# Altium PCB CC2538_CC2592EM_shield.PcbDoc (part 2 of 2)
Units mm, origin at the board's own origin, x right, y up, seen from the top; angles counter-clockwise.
Board outline 41.63 x 56.78 mm, 4 copper layers (TOP, L2, L3, BOTTOM), stack 1.596 mm thick; 77 components, 70 nets, 284 pads, 581 vias.
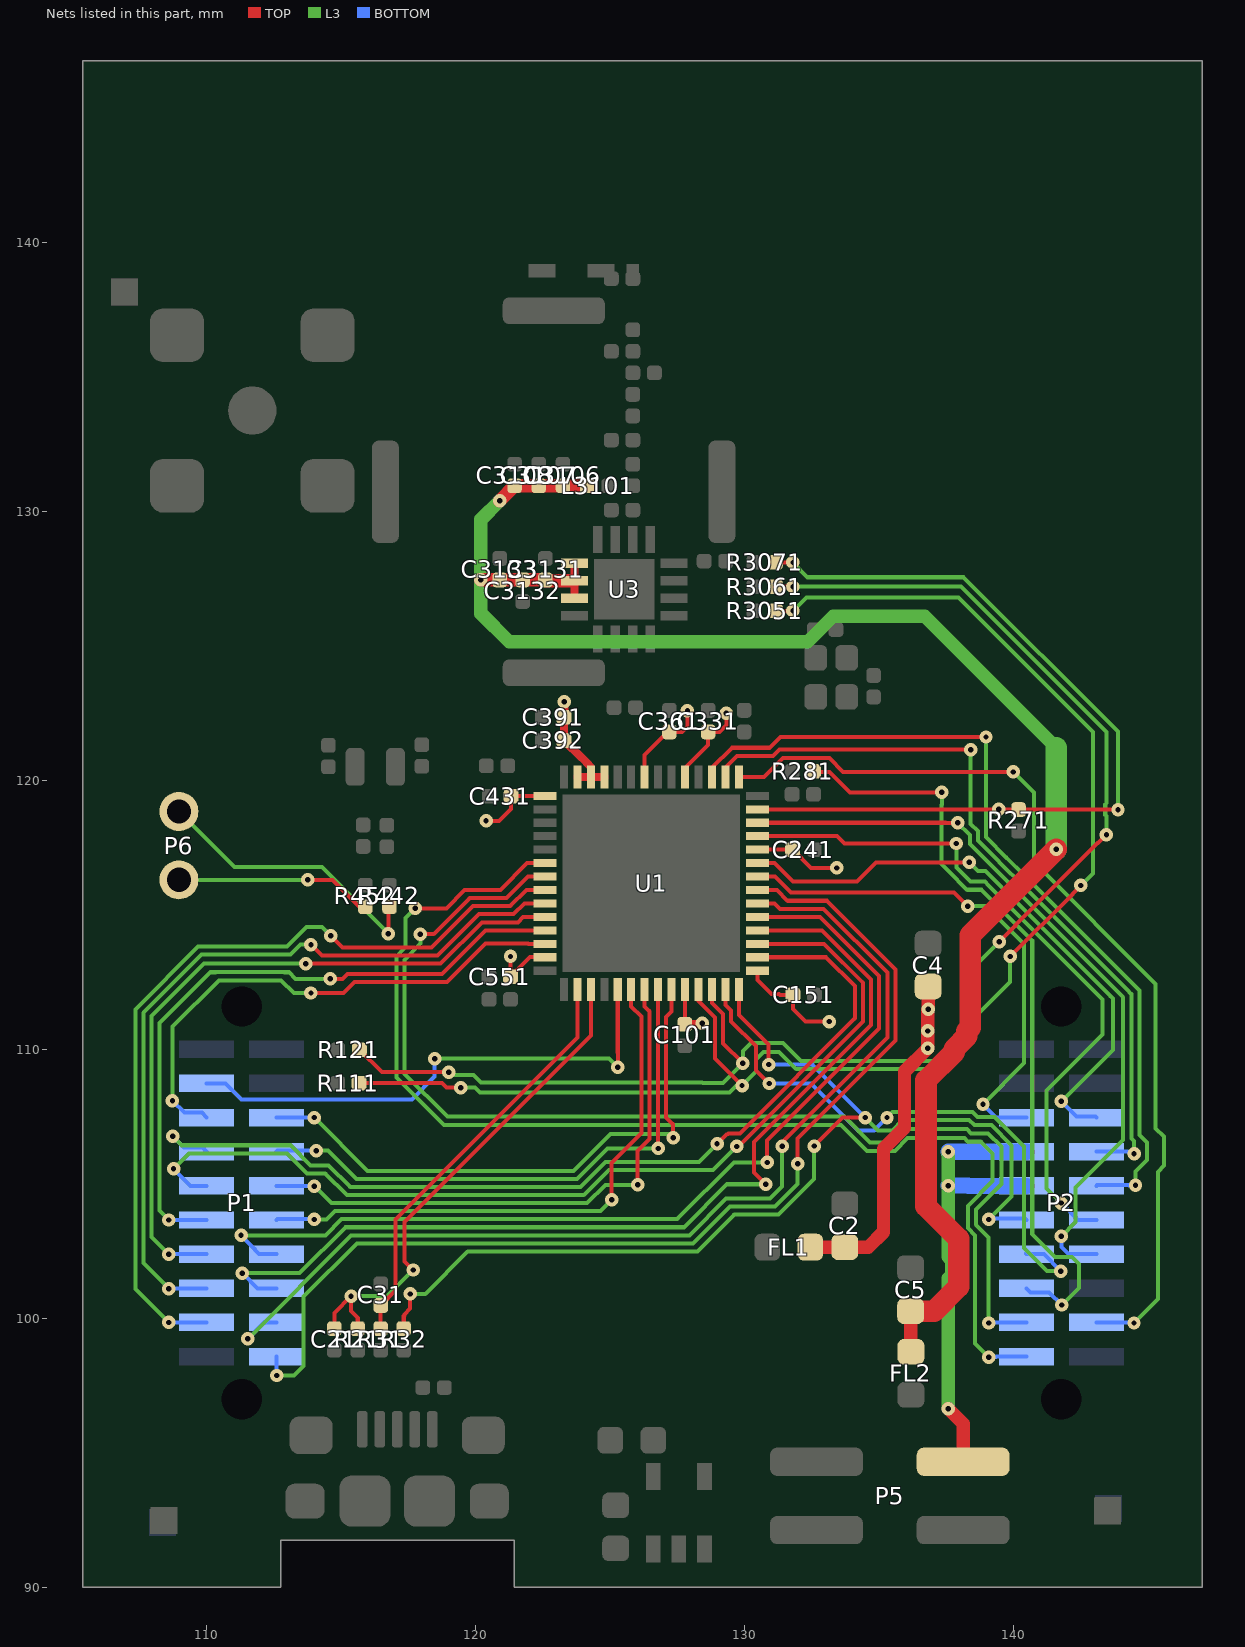
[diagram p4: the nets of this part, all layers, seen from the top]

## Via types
v1: diameter 0.5, hole 0.2, TOP to BOTTOM, 581 vias

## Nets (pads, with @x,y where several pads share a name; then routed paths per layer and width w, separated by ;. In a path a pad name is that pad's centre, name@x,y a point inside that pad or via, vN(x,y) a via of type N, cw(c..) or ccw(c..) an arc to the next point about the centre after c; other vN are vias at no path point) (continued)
NRESET: P2.15 R281.1 | length 28.8
  TOP w0.15: R281.1@132.57,120.33 132.59,120.31 133.17,120.31 133.93,119.55 v1(137.34,119.55)
  L3 w0.15: v1(137.34,119.55) 137.34,119.098 137.33,119.088 137.33,116.884 137.585,116.629 ; 137.585,116.628 138.283,115.93 138.808,115.93 ; 138.81,115.929 138.833,115.905 139.764,114.974 ; 139.765,114.974 140.7,114.039 140.7,103.13 141.55,102.28 142.17,102.28 142.44,102.01 142.44,101.13 v1(141.8,100.49) ; 138.808,115.93 138.809,115.929
  BOTTOM w0.15: P2.15@140.48,101.11 140.63,100.96 141.33,100.96 v1(141.8,100.49)
PA0: P1.7 U1.16 | length 35.5
  TOP w0.15: v1(128.98,106.48) 129.33,106.829 129.379,106.851 129.398,106.87 129.828,106.87 134.11,111.152 134.11,112.347 133.037,113.42 U1.16@130.49,113.42
  L3 w0.15: v1(108.74,106.76) 109.07,106.43 113.121,106.43 113.866,105.685 114.536,105.685 115.341,104.88 123.899,104.88 124.829,105.81 128.31,105.81 v1(128.98,106.48)
  BOTTOM w0.15: v1(108.74,106.76) 109.16,106.34 109.85,106.34 P1.7@110,106.19
PA1: P1.9 U1.17 | length 36.6
  TOP w0.15: v1(129.71,106.385) 129.716,106.39 129.773,106.39 134.41,111.027 134.41,112.472 132.962,113.92 U1.17@130.49,113.92
  L3 w0.15: v1(108.77,105.55) 109.35,106.13 112.996,106.13 113.741,105.385 114.411,105.385 115.216,104.58 124.024,104.58 124.954,105.51 128.836,105.51 v1(129.71,106.385)
  BOTTOM w0.15: v1(108.77,105.55) 109.4,104.92 P1.9@110,104.92
PA2: P1.16 U1.18 | length 36.9
  TOP w0.15: U1.18@130.49,114.42 132.887,114.42 134.71,112.597 134.71,110.902 130.36,106.552 130.36,105.41 v1(130.79,104.98)
  L3 w0.15: v1(111.33,101.674) 113.454,101.674 115.16,103.38 127.75,103.38 129.35,104.98 v1(130.79,104.98)
  BOTTOM w0.15: v1(111.33,101.674) 111.894,101.11 P1.16@112.604,101.11
PA3: P1.14 U1.19 | length 36.4
  TOP w0.15: U1.19@130.49,114.921 132.811,114.921 135.01,112.722 135.01,110.777 133.745,109.511 ; v1(130.84,105.79) 130.84,106.607 133.744,109.511
  L3 w0.15: v1(111.28,103.082) 114.422,103.082 115.02,103.68 127.5,103.68 129.61,105.79 v1(130.84,105.79)
  BOTTOM w0.15: v1(111.28,103.082) 111.8,102.562 111.8,102.53 111.95,102.38 P1.14@112.604,102.38
PA4: P1.18 U1.20 | length 39
  TOP w0.15: U1.20@130.49,115.421 131.118,115.421 131.318,115.221 132.936,115.221 135.311,112.846 135.311,110.441 131.4,106.53 v1(131.4,106.39)
  L3 w0.15: v1(111.53,99.23) 115.37,103.07 115.456,103.07 115.466,103.08 127.95,103.08 129.32,104.45 130.951,104.45 131.4,104.902 v1(131.4,106.39)
  BOTTOM w0.15: v1(111.53,99.23) 112.14,99.84 P1.18@112.604,99.84
PA5: P1.20 U1.21 | length 40.4
  TOP w0.15: U1.21@130.49,115.919 131.211,115.919 131.609,115.521 133.061,115.521 135.611,112.971 135.611,110.316 131.98,106.685 v1(131.98,105.74)
  L3 w0.15: v1(112.61,97.868) 113.252,97.868 113.61,98.226 113.61,100.8 115.59,102.78 128.09,102.78 129.46,104.15 131.143,104.15 131.98,104.987 v1(131.98,105.74)
  BOTTOM w0.15: P1.20@112.604,98.57 112.604,98.086 112.61,98.08 v1(112.61,97.868)
PA6: P2.5 U1.22 | length 19.4
  TOP w0.15: U1.22@130.49,116.419 131.141,116.419 131.73,115.83 137.79,115.83 v1(138.3,115.32)
  L3 w0.15: v1(138.3,115.32) 138.993,115.32 139.639,114.674 ; v1(138.87,107.95) 140.4,109.48 140.4,113.914 139.64,114.674
  BOTTOM w0.15: v1(138.87,107.95) 139.36,107.46 P2.5@140.48,107.46
PA7: P2.6 U1.23 | length 22.1
  TOP w0.15: U1.23@130.49,116.92 131.118,116.92 131.798,116.24 134.179,116.24 134.889,116.95 v1(138.36,116.95)
  L3 w0.15: v1(138.36,116.95) 138.68,116.63 138.958,116.63 139.059,116.529 139.061,116.529 139.283,116.306 140.014,115.574 ; 140.015,115.574 143.62,111.969 ; v1(141.78,108.06) 143.7,109.98 143.7,111.888 143.62,111.968
  BOTTOM w0.15: v1(141.78,108.06) 142.34,107.5 143.044,107.5 P2.6@143.084,107.46
PB0: P1.3 U1.5 | length 19.6
  TOP w0.15: U1.5@125.288,112.221 125.288,109.87 125.29,109.868 v1(125.29,109.33)
  L3 w0.15: v1(118.48,109.65) 124.97,109.65 v1(125.29,109.33)
  BOTTOM w0.15: P1.3@110,108.73 110.7,108.73 111.3,108.13 117.63,108.13 118.48,108.98 v1(118.48,109.65)
PB1: P1.5 U1.54 | length 19.8
  TOP w0.15: v1(113.88,112.09) 115.084,112.09 115.491,112.497 115.512,112.501 118.793,112.501 118.796,112.504 118.879,112.504 118.881,112.506 118.946,112.506 120.365,113.925 121.955,113.925 121.96,113.92 U1.54@122.588,113.92
  L3 w0.15: v1(108.73,108.08) 108.73,110.84 110.454,112.564 112.77,112.564 113.244,112.09 v1(113.88,112.09)
  BOTTOM w0.15: v1(108.73,108.08) 109.17,107.64 109.82,107.64 P1.5@110,107.46
PB2: P1.11 U1.53 | length 24.8
  TOP w0.15: v1(114.6,112.62) 115.052,112.62 115.233,112.801 118.668,112.801 118.671,112.804 118.754,112.804 120.369,114.419 121.664,114.419 121.665,114.42 U1.53@122.588,114.42
  L3 w0.15: v1(108.598,103.65) 108.25,103.998 108.25,110.97 110.143,112.863 110.328,112.863 110.329,112.864 112.895,112.864 ; v1(114.6,112.62) 113.31,112.62 113.067,112.863 112.896,112.863 ; 112.895,112.864 112.896,112.863
  BOTTOM w0.15: v1(108.598,103.65) P1.11@110,103.65
PB3: P1.13 U1.52 | length 26.7
  TOP w0.15: v1(113.68,113.18) 118.705,113.18 120.244,114.719 121.539,114.719 121.54,114.72 121.57,114.72 121.771,114.921 U1.52@122.588,114.921
  L3 w0.15: v1(108.59,102.38) 107.95,103.02 107.95,111.233 109.897,113.18 v1(113.68,113.18)
  BOTTOM w0.15: v1(108.59,102.38) P1.13@110,102.38
PB4: P1.15 U1.51 | length 29
  TOP w0.15: v1(113.88,113.89) 114.29,113.48 118.58,113.48 120.12,115.02 121.415,115.02 121.816,115.421 U1.51@122.588,115.421
  L3 w0.15: v1(108.598,101.1) 107.649,102.049 107.649,111.357 109.812,113.52 113.114,113.52 113.484,113.89 v1(113.88,113.89)
  BOTTOM w0.15: v1(108.598,101.1) 108.763,101.1 108.773,101.11 P1.15@110,101.11
PB5: P1.17 U1.50 | length 31.3
  TOP w0.15: v1(114.61,114.22) 115.05,113.78 118.37,113.78 119.91,115.32 121.29,115.32 121.889,115.919 U1.50@122.588,115.919
  L3 w0.15: v1(108.598,99.84) 107.35,101.088 107.35,101.923 107.349,101.924 107.349,111.482 109.687,113.82 112.989,113.82 113.709,114.54 114.29,114.54 v1(114.61,114.22)
  BOTTOM w0.15: v1(108.598,99.84) P1.17@110,99.84
PB6/JTAG_TDI: P2.17 U1.49 | length 43.3
  TOP w0.15: v1(117.95,114.28) 118.442,114.28 118.472,114.31 118.475,114.31 119.785,115.62 121.159,115.62 121.958,116.419 U1.49@122.588,116.419
  L3 w0.15: v1(117.95,114.28) 117.96,114.27 117.96,113.925 117.36,113.325 117.36,109.082 118.952,107.49 133.711,107.49 134.671,106.53 135.475,106.53 135.945,107 135.99,107 136.02,107.03 138.268,107.03 138.423,106.875 139.055,106.875 139.55,106.38 139.55,104.993 138.603,104.046 138.603,103.473 139.078,102.998 v1(139.078,99.82)
  BOTTOM w0.15: v1(139.078,99.82) 139.27,99.82 139.29,99.84 P2.17@140.48,99.84
PB7/JTAG_TDO: P2.19 U1.48 | length 45.5
  TOP w0.15: v1(117.76,115.24) 118.912,115.24 119.592,115.92 120.92,115.92 121.92,116.92 U1.48@122.588,116.92
  L3 w0.15: v1(117.76,115.24) 117.402,114.882 117.402,113.793 117.06,113.45 117.06,108.957 118.827,107.19 133.586,107.19 134.556,106.22 135.59,106.22 136.07,106.7 138.173,106.7 138.298,106.575 138.785,106.575 139.23,106.13 139.23,105.098 138.303,104.171 138.303,103.348 138.571,103.08 138.571,99.057 v1(139.078,98.55)
  BOTTOM w0.15: v1(139.078,98.55) 139.35,98.55 139.37,98.57 P2.19@140.48,98.57
PC0: P2.11 R32.2 U1.14 | length 40.1
  TOP w0.15: R32.2@117.33,99.61 117.33,100.087 117.35,100.107 117.35,100.14 117.57,100.36 v1(117.57,100.9) ; U1.14@129.789,112.221 129.789,111.576 129.795,111.57 129.795,111.549 129.797,111.547 129.797,111.399 129.801,111.37 129.802,111.364 129.802,111.278 130.9,110.18 v1(130.9,109.43) ; v1(132.59,106.4) 133.65,107.46 v1(134.49,107.46)
  L3 w0.15: v1(117.57,100.9) 118.13,100.9 119.71,102.48 128.25,102.48 129.62,103.85 131.268,103.85 132.585,105.167 132.585,105.697 132.59,105.702 v1(132.59,106.4) ; v1(134.49,107.46) 134.965,106.985 135.497,106.985 135.882,107.37 138.353,107.37 138.548,107.175 139.18,107.175 139.93,106.425 139.93,104.522 v1(139.078,103.67)
  BOTTOM w0.15: v1(130.9,109.43) 132.52,109.43 v1(134.49,107.46) ; v1(139.078,103.67) 139.22,103.67 139.25,103.7 140.43,103.7 P2.11@140.48,103.65
PC1: P2.13 U1.13 | length 22.2
  TOP w0.15: U1.13@129.289,112.221 129.289,111.651 129.495,111.445 129.495,111.424 129.497,111.422 129.497,111.378 129.502,111.342 129.502,111.038 130.425,110.115 130.425,109.218 v1(130.918,108.725)
  L3 w0.15: v1(135.3,107.46) 135.51,107.67 138.478,107.67 138.673,107.475 139.305,107.475 140.4,106.38 140.4,102.603 141.253,101.75 v1(141.76,101.75)
  BOTTOM w0.15: v1(130.918,108.725) 132.475,108.725 133.96,107.241 134.216,106.985 134.825,106.985 v1(135.3,107.46) ; P2.13@140.46,102.4 P2.13@140.48,102.38 141.13,102.38 v1(141.76,101.75)
PC2: R121.1 R3061.1 U1.12 | length 55.7
  TOP w0.15: R121.1@115.68,109.98 115.685,109.98 116.515,109.15 v1(119.01,109.15) ; U1.12@128.788,112.221 128.788,111.727 129.202,111.313 129.202,110.218 v1(129.94,109.48) ; R3061.1@131.15,127.2 v1(131.802,127.2) ; v1(139.48,114) 140.068,114.588 140.068,114.6 143.128,117.66 143.14,117.66 v1(143.46,117.98)
  L3 w0.15: v1(119.01,109.15) 119.115,109.045 119.932,109.045 120.207,108.77 128.428,108.77 128.453,108.745 129.205,108.745 v1(129.94,109.48) 129.94,109.932 130.248,110.24 131.427,110.24 131.709,109.959 132.103,109.565 137.055,109.565 138.29,110.8 138.29,112.81 v1(139.48,114) ; v1(131.802,127.2) 138.05,127.2 143.46,121.79 143.46,119.152 143.415,119.107 143.415,118.713 143.46,118.668 v1(143.46,117.98)
PC3: R111.1 R3051.1 U1.11 | length 56.2
  TOP w0.15: R111.1@115.67,108.74 118.748,108.74 118.918,108.57 v1(119.45,108.57) ; U1.11@128.29,112.221 128.29,111.8 128.902,111.188 128.902,109.658 v1(129.91,108.65) ; R3051.1@131.15,126.3 v1(131.802,126.3) ; v1(139.88,113.45) 142.19,115.76 142.19,115.77 v1(142.51,116.09)
  L3 w0.15: v1(119.45,108.57) 119.982,108.57 120.162,108.39 129.44,108.39 129.7,108.65 v1(129.91,108.65) ; v1@129.858,108.57 129.91,108.622 v1(129.91,108.65) ; v1(131.802,126.3) 132.302,126.8 137.96,126.8 142.96,121.8 142.96,121.092 142.965,121.087 142.965,120.693 142.96,120.688 142.96,116.54 v1(142.51,116.09) ; v1(139.88,113.45) 139.88,112.508 138.59,111.218 138.59,110.67 137.185,109.265 131.925,109.265 131.285,109.905 130.703,109.905 130.425,109.627 130.425,109.165 v1(129.91,108.65)
PC4: P1.6 U1.9 | length 21.9
  TOP w0.15: U1.9@127.289,112.221 127.29,111.403 127.09,111.203 127.09,107.47 127.35,107.21 v1(127.35,106.715)
  L3 w0.15: v1(114.006,107.46) 115.986,105.48 123.648,105.48 124.578,106.41 ; 124.579,106.41 124.819,106.65 125.019,106.849 127.216,106.849 v1(127.35,106.715)
  BOTTOM w0.15: P1.6@112.604,107.46 v1(114.006,107.46)
PC5: P1.8 U1.8 | length 21
  TOP w0.15: U1.8@126.789,112.221 126.789,111.593 126.79,111.592 v1(126.79,106.31)
  L3 w0.15: v1(114.07,106.23) 114.522,106.23 115.572,105.18 123.773,105.18 124.703,106.11 ; 124.704,106.11 124.904,106.31 v1(126.79,106.31)
  BOTTOM w0.15: P1.8@112.604,106.19 112.644,106.23 v1(114.07,106.23)
PC6: P1.10 U1.7 | length 21.5
  TOP w0.15: v1(126.03,104.96) 126.03,106.222 126.47,106.662 126.47,111.412 126.289,111.593 U1.7@126.289,112.221
  L3 w0.15: v1(114.006,104.91) 114.636,104.28 124.15,104.28 124.83,104.96 v1(126.03,104.96)
  BOTTOM w0.15: P1.10@112.604,104.92 113.996,104.92 v1(114.006,104.91)
PC7: P1.12 U1.6 | length 21.2
  TOP w0.15: v1(125.058,104.398) 125.058,105.768 126.17,106.88 126.17,111.212 125.789,111.593 U1.6@125.788,112.221
  L3 w0.15: v1(114.005,103.67) 114.457,103.67 114.767,103.98 124.64,103.98 v1(125.058,104.398)
  BOTTOM w0.15: P1.12@112.604,103.65 112.634,103.68 113.79,103.68 113.8,103.67 v1(114.005,103.67)
PD0: P2.12 U1.25 | length 26.1
  TOP w0.15: U1.25@130.49,117.921 133.449,117.921 133.72,117.65 v1(137.88,117.65)
  L3 w0.15: v1(137.88,117.65) 137.88,117.198 137.885,117.193 137.885,116.753 138.163,116.475 ; 138.164,116.475 138.409,116.23 138.933,116.23 138.934,116.229 138.936,116.229 139.07,116.093 139.889,115.274 ; 139.89,115.274 143.32,111.844 143.32,110.55 141.23,108.46 141.23,104.83 v1(141.78,104.28)
  BOTTOM w0.15: v1(141.78,104.28) 142.41,103.65 P2.12@143.084,103.65
PD1: P2.14 U1.26 | length 28.1
  TOP w0.15: U1.26@130.49,118.421 137.477,118.421 137.478,118.42 v1(137.93,118.42)
  L3 w0.15: v1(137.93,118.42) 138.38,117.97 138.38,117.633 139.184,116.829 139.186,116.829 139.496,116.519 140.139,115.875 143.92,112.094 ; v1(141.78,103.04) 142.31,103.57 142.31,104.859 143.84,106.389 ; 143.84,106.39 144.08,106.63 144.08,111.933 143.92,112.093
  BOTTOM w0.15: v1(141.78,103.04) 141.78,102.64 142.04,102.38 P2.14@143.084,102.38
PD2: R271.2 R3071.1 U1.27 | length 31.6
  TOP w0.15: U1.27@130.49,118.919 139.007,118.919 139.008,118.92 v1(139.46,118.92) 140.18,118.92 R271.2@140.19,118.91 v1(143.89,118.91) ; R3071.1@131.15,128.1 v1(131.802,128.1)
  L3 w0.15: v1(131.802,128.1) 132.352,127.55 138.15,127.55 143.89,121.81 v1(143.89,118.91)
PD3: P2.18 U1.29 | length 35.4
  TOP w0.15: U1.29@129.789,120.12 130.73,120.12 131.435,120.825 133.155,120.825 133.67,120.31 v1(140,120.31)
  L3 w0.15: v1(140,120.31) 140.76,119.55 140.76,116.957 145.29,112.427 145.29,107.06 145.6,106.75 145.6,105.67 145.37,105.44 145.37,100.705 v1(144.485,99.82)
  BOTTOM w0.15: P2.18@143.084,99.84 144.42,99.84 144.44,99.82 v1(144.485,99.82)
PD4: P2.8 U1.30 | length 28.7
  TOP w0.15: U1.30@129.289,120.12 129.289,120.469 129.73,120.91 131.061,120.91 131.276,121.125 131.285,121.125 131.3,121.14 v1(138.41,121.14)
  L3 w0.15: v1(138.41,121.14) 138.41,118.38 138.68,118.11 138.68,117.758 139.309,117.129 139.311,117.129 139.62,116.82 ; 139.621,116.82 140.264,116.176 ; 140.265,116.176 141.9,114.542 141.9,114.539 144.22,112.219 144.38,112.058 ; 144.38,112.057 144.39,112.047 144.39,106.685 144.486,106.589 v1(144.486,106.11)
  BOTTOM w0.15: P2.8@143.084,106.19 144.25,106.19 144.33,106.11 v1(144.486,106.11)
PD5: P2.10 U1.31 | length 31.8
  TOP w0.15: U1.31@128.788,120.12 128.788,120.469 129.531,121.21 130.936,121.21 131.151,121.425 131.155,121.425 131.345,121.615 138.523,121.615 138.528,121.61 v1(138.98,121.61)
  L3 w0.15: v1(138.98,121.61) 138.98,117.886 139.746,117.12 140.389,116.476 142.2,114.667 144.69,112.177 144.69,106.81 144.961,106.539 144.961,105.881 144.54,105.461 v1(144.54,104.94)
  BOTTOM w0.15: P2.10@143.084,104.92 143.114,104.95 144.29,104.95 144.3,104.94 v1(144.54,104.94)
PD6: P6.1 R442.1 | length 10.7
  TOP w0.15: v1(116.76,114.3) 116.76,115.26 R442.1@116.8,115.3
  L3 w0.15: P6.1@108.97,118.84 111.035,116.775 114.285,116.775 v1(116.76,114.3)
PD7: P6.2 R452.1 | length 7.5
  TOP w0.15: v1(113.76,116.3) 114.676,116.3 115.81,115.166 115.81,115.26 115.85,115.3 R452.1@115.9,115.3
  L3 w0.15: P6.2@108.97,116.3 v1(113.76,116.3)
USB_N: C21.1 R21.1 U1.3 | length 18.9
  TOP w0.15: C21.1@114.75,99.61 114.75,100.2 v1(115.37,100.82) 115.37,100.26 115.62,100.01 R21.1@115.62,99.61 ; v1(117.68,101.79) 117.36,102.11 117.36,103.576 124.29,110.506 U1.3@124.29,112.221
  L3 w0.15: v1(115.37,100.82) 116.71,100.82 v1(117.68,101.79)
USB_P: C31.1 R31.1 U1.2 | length 15.6
  TOP w0.15: R31.1@116.47,99.61 116.47,100.46 C31.1@116.48,100.47 116.48,100.475 117.025,101.02 117.025,103.666 123.79,110.431 123.79,111.592 123.789,111.593 U1.2@123.789,112.221
VDD_CC2538: C2.1 C4.1 C101.1 C151.1 C241.1 C331.1 C361.1 C391.1 C392.1 C431.1 C551.1 FL1.1 U1.10 U1.15 U1.24 U1.33 U1.36 U1.39 U1.40 U1.41 U1.43 U1.55 | length 38.1
  TOP w0.15: v1(120.39,118.49) 120.872,118.49 121.32,118.938 C431.1@121.32,119.41 121.797,119.41 121.806,119.419 U1.43@122.588,119.419 ; v1(121.3,113.45) 121.3,112.71 121.29,112.7 C551.1@121.3,112.7 122.03,113.43 122.578,113.43 U1.55@122.588,113.42 ; C391.1@123.29,122.33 C391.1@123.29,122.34 ; U1.36@126.289,120.12 126.289,120.934 127.145,121.79 127.2,121.79 C361.1@127.21,121.8 127.682,121.8 127.88,121.998 v1(127.88,122.58) ; C101.1@127.78,110.93 127.78,111.407 127.79,111.417 U1.10@127.79,112.221 ; U1.33@127.79,120.12 127.79,120.453 128.65,121.313 C331.1@128.65,121.8 129.072,121.8 129.327,122.055 129.327,122.493 v1(129.32,122.5) ; v1@128.395,110.93 v1(128.427,110.962) ; U1.15@130.49,112.919 130.49,112.567 131.012,112.046 131.288,112.046 131.314,112.02 C151.1@131.8,112.02 131.8,111.498 132.268,111.03 v1(133.15,111.03) ; U1.24@130.49,117.42 131.795,117.42 132.475,116.74 v1(133.43,116.74)
  TOP w0.3: v1(123.3,122.92) 123.3,122.34 123.29,122.33 C392.1@123.29,121.48 123.295,121.48 123.952,120.823 123.966,120.823 124.216,120.573 124.216,120.559 124.29,120.485 U1.40@124.29,120.12 ; U1.41@123.789,120.12 U1.40@124.29,120.12 ; U1.39@124.79,120.12 U1.40@124.29,120.12 ; C101.1@127.78,110.93 v1@128.395,110.93
  TOP w0.5: FL1.1@132.45,102.64 134.608,102.64 135.17,103.202 135.17,106.3 135.95,107.08 135.95,109.17 v1(136.82,110.04) v1(136.82,110.68) 136.82,111.47 v1(136.84,111.49) 136.84,112.32 C4.1@136.83,112.33
  L3 w0.15: v1@128.42,110.955 v1(128.427,110.962)
VDD_CC2592: C5.1 C3106.1 C3107.1 C3108.1 C3131.1 C3132.1 C3133.1 FL2.1 L3101.1 U3.13 U3.14 U3.15 | length 63.2
  TOP w0.15: C5.1@136.18,100.26 C5.1@136.19,100.26
  TOP w0.3: U3.15@123.675,126.775 U3.14@123.675,127.425 U3.13@123.675,128.075
  TOP w0.5: v1(120.2,127.45) C3133.1@120.9,127.45 C3132.1@121.75,127.45 C3131.1@122.6,127.45 122.625,127.425 U3.14@123.675,127.425 ; v1(120.9,130.4) C3108.1@121.45,130.95 C3107.1@122.35,130.95 C3106.1@123.25,130.95 L3101.1@124.15,130.95 ; FL2.1@136.19,98.74 FL2.1@136.19,98.75 C5.1@136.19,100.26
  TOP w0.8: C5.1@136.19,100.26 137.05,100.26 137.96,101.17 137.96,102.95 136.75,104.16 136.75,108.838 137.8,109.888 137.8,110.008 138.27,110.478 138.27,110.67 138.39,110.79 138.39,114.232 141.037,116.879 141.039,116.879 v1(141.59,117.43)
  L3 w0.5: v1(120.9,130.4) 120.2,129.7 v1(120.2,127.45) 120.2,126.2 121.25,125.15 132.35,125.15 133.3,126.1 136.7,126.1 141.59,121.21
  L3 w0.8: v1(141.59,117.43) 141.59,121.21
VDD_EB: P2.7 P2.9 P5.2 | length 17.7
  TOP w0.5: v1(137.58,96.63) 138.13,96.08 P5.2@138.13,94.66
  L3 w0.5: v1(137.58,96.63) 137.58,101.483 137.707,101.61 137.707,102.15 137.58,102.277 v1(137.58,104.93) v1(137.58,106.19)
  BOTTOM w0.6: v1(137.58,104.93) 138.312,104.93 138.322,104.92 P2.9@140.48,104.92 ; v1(137.58,106.19) P2.7@140.48,106.19
pads on no net: "P1. " "P2. " Designator1.1 Designator1.2 Designator1.3 FIDU1.1 FIDU2.1 FIDU3.1 FIDU4.1 FIDU5.1 FIDU6.1 P2.3 P5.4 U2.4

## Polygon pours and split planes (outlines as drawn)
VDD_CC2538 on L3 (solid, pour order 38): 724 vertices, not listed, extent 120,109.7 138.3,124.748
GND on L3 (solid, pour order 36): 132 vertices, not listed, extent 125.372,103.907 128.645,105.283
GND on L3 (solid, pour order 34): 66 vertices, not listed, extent 125.653,108.972 129.473,109.471
GND on L3 (solid, pour order 32): 77 vertices, not listed, extent 138.529,111.619 139.653,113.423
GND on L3 (solid, pour order 30): 107 vertices, not listed, extent 140.927,108.619 143.093,111.85
GND on L3 (solid, pour order 28): 140 vertices, not listed, extent 138.577,108.947 140.173,112.339
GND on L3 (solid, pour order 26): 67 vertices, not listed, extent 140.927,112.293 142.044,113.779
GND on L3 (solid, pour order 24): 149 vertices, not listed, extent 136.936,116.165 142.738,126.573
GND on L3 (solid, pour order 22): 378 vertices, not listed, extent 132.638,117.216 141.038,125.698
GND on L3 (solid, pour order 20): 162 vertices, not listed, extent 105.901,90.501 146.499,139.2
N362623 on L3 (solid, pour order 0): 91 vertices, not listed, extent 123.45,113 129.7,120.609
GND on TOP (solid, pour order 14): 208 vertices, not listed, extent 130.938,111.135 133.883,113.193
GND on TOP (solid, pour order 12): 348 vertices, not listed, extent 133.44,107.687 138.122,115.603
GND on TOP (solid, pour order 10): 181 vertices, not listed, extent 132.215,116.467 137.642,117.694
GND on TOP (solid, pour order 8): 127 vertices, not listed, extent 132.066,119.146 133.872,120.083
GND on TOP (solid, pour order 6): 739 vertices, not listed, extent 105.901,90.501 146.499,139.2
GND on TOP (solid, pour order 4): 121.45,138.2 121.45,139.2 125.2,139.2 125.2,138.2 121.45,138.2
N355972 on TOP (solid, pour order 2): 31 vertices, not listed, extent 111.668,132.983 113.305,134.517
GND on L2 (solid, pour order 16): 168 vertices, not listed, extent 105.901,90.501 146.499,139.2
GND on BOTTOM (solid, pour order 18): 217 vertices, not listed, extent 105.901,90.501 146.499,139.2
no net on Top Overlay (solid): 115 vertices, not listed, extent 131.837,140.412 133.153,141.91
no net on Top Overlay (solid): 113 vertices, not listed, extent 135.036,138.652 136.075,139.835
no net on Top Overlay (solid): 113 vertices, not listed, extent 142.424,138.652 143.464,139.835
no net on Top Overlay (solid): 112 vertices, not listed, extent 133.986,140.412 135.144,141.603
no net on Top Overlay (solid): 99 vertices, not listed, extent 135.122,140.412 136.31,141.603
no net on Top Overlay (solid): 313 vertices, not listed, extent 136.127,138.649 137.351,139.833
no net on Top Overlay (solid): 164 vertices, not listed, extent 137.248,138.652 138.485,139.839
no net on Top Overlay (solid): 169 vertices, not listed, extent 138.545,138.65 140.047,139.839
no net on Top Overlay (solid): 128 vertices, not listed, extent 140.129,138.65 141.161,139.839
no net on Top Overlay (solid): 128 vertices, not listed, extent 132.934,140.412 133.965,141.601
no net on Top Overlay (solid): 92 vertices, not listed, extent 132.238,138.65 132.76,140.196
no net on Top Overlay (solid): 139 vertices, not listed, extent 132.823,138.652 134.048,139.839
no net on Top Overlay (solid): 139 vertices, not listed, extent 141.172,138.652 142.397,139.839
no net on Top Overlay (solid): 188 vertices, not listed, extent 143.516,138.62 144.485,139.858
no net on Top Overlay (solid): 188 vertices, not listed, extent 134.072,138.614 135.042,139.851
no net on Top Overlay (solid): 188 vertices, not listed, extent 136.292,140.376 137.262,141.614
no net on Top Overlay (solid): 199 vertices, not listed, extent 127.598,139.02 131.321,142.65
no net on Top Overlay (solid): 129.856,142.031 129.947,142.429 130.363,142.429 130.272,142.031 129.856,142.031
no net on Top Overlay (solid): 129.856,141.975 129.539,140.407 129.955,140.407 130.272,141.975 129.856,141.975
no net on Top Overlay (solid): 115 vertices, not listed, extent 131.837,140.412 133.153,141.91
no net on Top Overlay (solid): 113 vertices, not listed, extent 135.036,138.652 136.075,139.835
no net on Top Overlay (solid): 113 vertices, not listed, extent 142.424,138.652 143.464,139.835
no net on Top Overlay (solid): 112 vertices, not listed, extent 133.986,140.412 135.144,141.603
no net on Top Overlay (solid): 99 vertices, not listed, extent 135.122,140.412 136.31,141.603
no net on Top Overlay (solid): 313 vertices, not listed, extent 136.127,138.649 137.351,139.833
no net on Top Overlay (solid): 164 vertices, not listed, extent 137.248,138.652 138.485,139.839
no net on Top Overlay (solid): 169 vertices, not listed, extent 138.545,138.65 140.047,139.839
no net on Top Overlay (solid): 128 vertices, not listed, extent 140.129,138.65 141.161,139.839
no net on Top Overlay (solid): 128 vertices, not listed, extent 132.934,140.412 133.965,141.601
no net on Top Overlay (solid): 92 vertices, not listed, extent 132.238,138.65 132.76,140.196
no net on Top Overlay (solid): 139 vertices, not listed, extent 132.823,138.652 134.048,139.839
no net on Top Overlay (solid): 139 vertices, not listed, extent 141.172,138.652 142.397,139.839
no net on Top Overlay (solid): 188 vertices, not listed, extent 143.516,138.62 144.485,139.858
no net on Top Overlay (solid): 188 vertices, not listed, extent 134.072,138.614 135.042,139.851
no net on Top Overlay (solid): 188 vertices, not listed, extent 136.292,140.376 137.262,141.614
no net on Top Overlay (solid): 199 vertices, not listed, extent 127.598,139.02 131.321,142.65
no net on Top Overlay (solid): 129.856,142.031 129.947,142.429 130.363,142.429 130.272,142.031 129.856,142.031
no net on Top Overlay (solid): 129.856,141.975 129.539,140.407 129.955,140.407 130.272,141.975 129.856,141.975
no net on Top Overlay (solid): 82 vertices, not listed, extent 110.568,139.099 113.186,144.095
no net on Top Overlay (solid): 82 vertices, not listed, extent 106.282,139.099 108.9,144.095
no net on Top Overlay (solid): 82 vertices, not listed, extent 110.568,139.099 113.186,144.095
no net on Top Overlay (solid): 82 vertices, not listed, extent 106.282,139.099 108.9,144.095

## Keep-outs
Keep-Out Layer:
  lines w0.025: 105.4,90 105.4,146.75 147,146.75 147,90 121.45,90 121.45,91.75 112.75,91.75 112.75,90 105.4,90

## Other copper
TOP:
  drawing of 1892 lines, arcs and shapes, not listed
L2:
  drawing of 314 lines, arcs and shapes, not listed
L3:
  drawing of 1097 lines, arcs and shapes, not listed
BOTTOM:
  drawing of 925 lines, arcs and shapes, not listed

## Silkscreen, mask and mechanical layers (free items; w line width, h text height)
Top Overlay:
  text "#REFDES" at 128,140.8 h0.02
  text "#REFDES" at 108.7,139.2 h0.02
Top Paste:
  drawing of 151 lines, arcs and shapes, not listed
Top Solder:
  drawing of 149 lines, arcs and shapes, not listed
NCLEGEND-1-4:
  circle w0.025: c116.645,60.078 r0.635
  lines w0.025: 105.23,49.372 228.04,49.372 ; 105.23,56.509 228.04,56.509 ; 105.23,63.646 228.04,63.646 ; 105.23,70.783 228.04,70.783 ; 105.23,77.92 228.04,77.92 ; 128.06,42.235 128.06,70.783 ; 176.082,42.235 176.082,70.783 ; 208.359,42.235 208.359,70.783 ; 105.23,42.235 105.23,84.42 228.04,84.42 228.04,42.235 105.23,42.235 ; 115.645,44.804 116.645,46.804 117.645,44.804 115.645,44.804 ; 116.645,52.04 cw(c116.645,52.94) 116.645,53.84 cw(c116.645,52.94) 116.645,52.04
  text "DRILL CHART: TOP to BOTTOM" at 133.615,79.658 h3.17
  text "ALL UNITS ARE IN MILLIMETERS" at 131.075,73.158 h3.17
  text "FIGURE" at 109.025,66.02 h3.17
  text "SIZE" at 146.991,66.02 h3.17
  text "PLATED" at 184.6,66.02 h3.17
  text "QTY" at 214.389,66.02 h3.17
  text "0.2" at 148.261,58.49 h3.17
  text "PLATED" at 184.6,58.49 h3.17
  text "581" at 214.389,58.49 h3.17
  text "1.1" at 148.261,51.353 h3.17
  text "PLATED" at 184.6,51.353 h3.17
  text "2" at 216.929,51.353 h3.17
  text "1.501" at 145.721,44.216 h3.17
  text "NON-PLATED" at 179.52,44.216 h3.17
  text "4" at 216.929,44.216 h3.17
AUTOSILK_TOP:
  text "Model: CC2538-CC2592EM" at 130.85,135.4 h0.64
  text "Revision:          2.0" at 130.85,134.613 h0.64
  text "FCC ID:  ZAT25382592EM" at 130.85,133.826 h0.64
  text "IC:    451H-25382592EM" at 130.85,133.039 h0.64
  text "PD7" at 110.59,119.21 h0.64
  text "PD6" at 110.59,116 h0.64
  text "CC2538-CC2592" at 127.78,96.85 h0.64
  text "VDD" at 131,95.5 h0.64
  text "EB power" at 140.23,94.4 h0.64
  text "USB power" at 130.9,92.85 h0.64
XSECTION_CHART:
  region: 105.708,200.269 126.028,200.269 126.028,207.129 105.708,207.129
  region: 105.708,193.311 126.028,193.311 126.028,196.839 105.708,196.839
  region: 105.708,167.439 126.028,167.439 126.028,170.967 105.708,170.967
  region: 105.708,157.149 126.028,157.149 126.028,164.009 105.708,164.009
  lines w0.025: 105.708,164.009 105.708,167.439 126.028,167.439 126.028,164.009 105.708,164.009 ; 105.708,170.967 105.708,193.311 126.028,193.311 126.028,170.967 105.708,170.967 ; 105.708,196.839 105.708,200.269 126.028,200.269 126.028,196.839 105.708,196.839
  text "___________________________" at 113.978,219.708 h3.17
  text "DESIGN CROSS SECTION CHART" at 115.248,219.708 h3.17
  text "TOTAL THICKNESS 1.596 MM" at 117.788,213.358 h3.17
  text "L1: TOP CONDUCTOR - COPPER 0.035 MM" at 126.028,202.896 h3.17
  text "*  DIELECTRIC - FR-4 0.175 MM" at 126.028,196.036 h3.17
  text "L2: L2 PLANE - COPPER 0.018 MM" at 126.028,191.303 h3.17
  text "*  DIELECTRIC - FR-4 1.14 MM" at 126.028,182.139 h3.17
  text "L3: L3 PLANE - COPPER 0.018 MM" at 126.028,167.634 h3.17
  text "*  DIELECTRIC - FR-4 0.175 MM" at 126.028,162.701 h3.17
  text "L4: BOTTOM CONDUCTOR - COPPER 0.035 MM" at 126.028,158.268 h3.17
AUTOSILK_BOTTOM:
  text "Max 3.6V" at 143.408,96.06 h0.64
DRAWING_ORIGIN:
  lines w0.025: -0.635,0 0.635,0 ; 0,-0.635 0,0.635
DIMENSION:
  lines w0.025: 105.4,148.3 126.05,148.3 ; 105.4,148.3 109.4,147.675 ; 105.4,148.3 109.4,148.925 ; 105.4,148.3 126.05,148.3 ; 105.4,148.3 109.4,147.675 ; 105.4,148.3 109.4,148.925 ; 109.4,147.675 109.4,148.925 ; 109.4,147.675 109.4,148.925 ; 126.05,148.3 147,148.3 ; 126.05,148.3 147,148.3 ; 143,147.675 143,148.925 ; 143,147.675 147,148.3 ; 143,147.675 143,148.925 ; 143,147.675 147,148.3 ; 143,148.925 147,148.3 ; 143,148.925 147,148.3 ; 155.025,94 156.275,94 ; 155.025,94 155.65,90 ; 155.025,94 156.275,94 ; 155.025,94 155.65,90 ; 155.025,142.75 156.275,142.75 ; 155.025,142.75 155.65,146.75 ; 155.025,142.75 156.275,142.75 ; 155.025,142.75 155.65,146.75 ; 155.65,90 155.65,119.907 ; 155.65,90 156.275,94 ; 155.65,90 155.65,119.907 ; 155.65,90 156.275,94 ; 155.65,119.907 155.65,146.75 ; 155.65,119.907 155.65,146.75 ; 155.65,146.75 156.275,142.75 ; 155.65,146.75 156.275,142.75 ; 105.4,146.406 105.4,150.8 105.4,146.406 ; 147,143.511 147,150.8 147,143.511 ; 148.401,146.75 158.15,146.75 148.401,146.75 ; 148.497,90 158.15,90 148.497,90
  text "41.6" at 120.145,149.887 h3.17
  text "41.6" at 120.145,149.887 h3.17
  text "56.8" at 154.063,114.002 h3.17 r90
  text "56.8" at 154.063,114.002 h3.17 r90
FILMMASKTOP:
  drawing of 149 lines, arcs and shapes, not listed
COPYRIGHTS:
  text "COPYRIGHTS 2012 @ DYNAMIC PRECISION" at 107.2,144.3 h0.2
  text "COPYRIGHTS 2012 @ DYNAMIC PRECISION" at 130.4,142.85 h0.2
DESIGNED_BY:
  text "JOANNA MINKIEWICZ" at 106.15,139.5 h0.2
  text "JOANNA MINKIEWICZ" at 127.35,138.75 h0.2
APPROVED_BY:
  text "ROBERT MITAL" at 106.15,139.9 h0.2
  text "ROBERT MITAL" at 127.35,139.15 h0.2
DESIGN_DATE:
  text "2012-08-23" at 106.15,139.15 h0.2
  text "2012-08-23" at 127.35,138.4 h0.2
